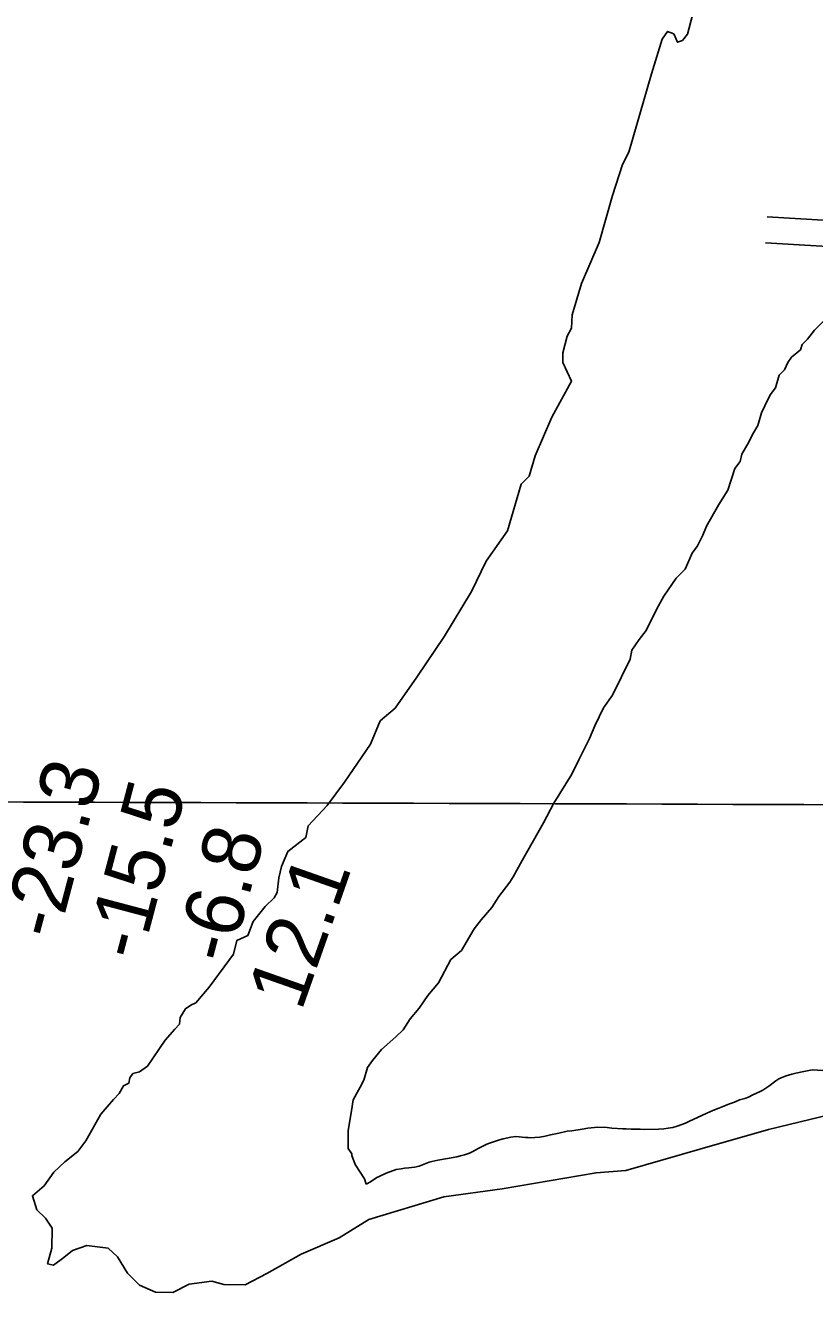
# Model space of a CAD drawing. Extents: x 3148686 to 3186545, y 916144 to 941516.
# Drawn here: x 3162509 to 3163416, y 933083 to 934539 of the extents above; entities that cross this region are included whole.
import ezdxf

# ---------------------------------------------------------------- set-up
doc = ezdxf.new("R2010")
doc.units = 0
for name, color, linetype in [('V-GRID-MAJR', 7, 'Continuous'), ('V-RIVR-EDGE', 7, 'Continuous'), ('V-RIVR-RANG', 7, 'Continuous'), ('V-ROAD-CNTR', 7, 'Continuous'), ('V-SITE-VEGE', 7, 'Continuous')]:
    doc.layers.add(name, color=color, linetype=linetype)

msp = doc.modelspace()

# ---------------------------------------------------------------- linework, layer by layer
at = {"layer": 'V-GRID-MAJR'}
msp.add_spline([(3152965.6, 933679.7), (3155575.1, 933670.5), (3160794.2, 933652.6), (3166013.2, 933635.6), (3171232.3, 933619.2), (3176451.4, 933603.7), (3181670.5, 933588.9), (3184280, 933581.8)], degree=3, dxfattribs=at)
at = {"layer": 'V-RIVR-EDGE'}
for points in [[(3162610.2, 933305.3), (3162616.9, 933312), (3162621.6, 933320.8), (3162627.9, 933323.9), (3162628.9, 933330.2), (3162632.6, 933334.8), (3162640.3, 933336.9), (3162649.2, 933343.6), (3162669.5, 933373.1), (3162680.9, 933386), (3162686.1, 933391.7), (3162686.7, 933399.5), (3162692.9, 933409.3), (3162699.1, 933413.5), (3162704.8, 933416.1), (3162720.4, 933434.2), (3162748, 933472), (3162752.2, 933488), (3162764.7, 933493.7), (3162770.9, 933509.8), (3162784.5, 933526.9), (3162794.9, 933536.7), (3162798.5, 933542.9), (3162800.1, 933560), (3162803.3, 933573), (3162810.6, 933590.1), (3162831.3, 933606.1), (3162834, 933619.6), (3162855.8, 933642.8), (3162875.6, 933669.8), (3162905.8, 933713.3), (3162916.7, 933740.2), (3162933.9, 933754.7), (3162958.9, 933790.4), (3162990.6, 933837.5), (3163021.9, 933888.8), (3163038.5, 933923.5), (3163063, 933958.7), (3163078.7, 934012.1), (3163088, 934021.4), (3163094.8, 934044.7), (3163114.1, 934089.3), (3163136.6, 934130.7), (3163126.7, 934152), (3163126.8, 934162.9), (3163131.5, 934182.1), (3163136.7, 934191.4), (3163137.3, 934206.9), (3163148.2, 934242.7), (3163168.6, 934289.8), (3163183.8, 934343.7), (3163195.3, 934379.5), (3163202.5, 934393.5), (3163228.7, 934483.6), (3163240.7, 934523.6), (3163247, 934532.4), (3163254.2, 934529.7), (3163258.4, 934519.9), (3163264.1, 934521.9), (3163269.8, 934529.2), (3163280.3, 934569.1)], [(3163469, 933296.4), (3163363.1, 933270.8), (3163284.3, 933248.2), (3163199.1, 933223.5), (3163164.9, 933221), (3163057, 933202.6), (3162990.1, 933193.4), (3162903.9, 933167.1), (3162869.6, 933146), (3162826, 933127.4), (3162786.5, 933105.2), (3162761.6, 933092.3), (3162737.2, 933092.4), (3162723.2, 933096.5), (3162697.3, 933093), (3162678.6, 933083.2), (3162658.4, 933083.7), (3162640.3, 933091.6), (3162626.3, 933105.6), (3162614.9, 933124.3), (3162604.1, 933134.2), (3162579.7, 933137.4), (3162563.1, 933131.7), (3162553.2, 933123.4), (3162541.3, 933114.6), (3162534.5, 933116.2), (3162539.2, 933134.3), (3162539.8, 933157.2), (3162532.1, 933168.6), (3162522.2, 933178.5), (3162517.1, 933194.6), (3162530.6, 933205.9), (3162541.5, 933221.5), (3162554.5, 933233.4), (3162569.1, 933245.3), (3162578.4, 933257.7), (3162595.6, 933288.2), (3162610.2, 933305.3)]]:
    msp.add_lwpolyline(points, dxfattribs=at)
at = {"layer": 'V-ROAD-CNTR'}
for points in [[(3163359.7, 934289.3), (3163482.6, 934282.1), (3164073.4, 934278.5), (3164714, 934271.7), (3165132.2, 934269.7), (3165570.2, 934275.6), (3166245.6, 934279.1), (3166867.8, 934288.1), (3167164.8, 934288.7), (3167686.9, 934273), (3168000.9, 934271.8), (3168168.6, 934286.1), (3168244.2, 934321), (3168298.4, 934368), (3168350.1, 934433.6), (3168384.1, 934490.5), (3168443.5, 934622.3), (3168480, 934725.3), (3168496.7, 934826), (3168498.8, 934894.8), (3168492.4, 935008.7), (3168468.4, 935145), (3168439.1, 935248.4)], [(3163361.5, 934319.2), (3163483.6, 934312.1), (3164073.6, 934308.5), (3164714.2, 934301.7), (3165132.1, 934299.7), (3165235.8, 934301.1)]]:
    msp.add_lwpolyline(points, dxfattribs=at)
at = {"layer": 'V-SITE-VEGE'}
for p, q in [((3163428.4, 934201.6), (3163416.1, 934189.2)), ((3163416.1, 934189.2), (3163407.9, 934178.8)), ((3163399.8, 934166.4), (3163389.5, 934158.1)), ((3163401.8, 934172.6), (3163399.8, 934166.4)), ((3163407.9, 934178.8), (3163401.8, 934172.6)), ((3163385.4, 934151.9), (3163381.4, 934143.7)), ((3163389.5, 934158.1), (3163385.4, 934151.9)), ((3163375.2, 934137.4), (3163371.2, 934123)), ((3163381.4, 934143.7), (3163375.2, 934137.4)), ((3163371.2, 934123), (3163365.1, 934114.7)), ((3163365.1, 934114.7), (3163359, 934102.3)), ((3163354.9, 934094.1), (3163350.9, 934079.6)), ((3163359, 934102.3), (3163354.9, 934094.1)), ((3163350.9, 934079.6), (3163344.7, 934069.3)), ((3163344.7, 934069.3), (3163340.7, 934061)), ((3163340.7, 934061), (3163332.5, 934046.6)), ((3163330.5, 934038.3), (3163324.4, 934030)), ((3163332.5, 934046.6), (3163330.5, 934038.3)), ((3163324.4, 934030), (3163316.3, 934005.3)), ((3163316.3, 934005.3), (3163306.1, 933988.7)), ((3163306.1, 933988.7), (3163291.8, 933964)), ((3163291.8, 933964), (3163287.7, 933953.6)), ((3163287.7, 933953.6), (3163281.6, 933941.2)), ((3163275.5, 933933), (3163267.4, 933914.4)), ((3163281.6, 933941.2), (3163275.5, 933933)), ((3163257.1, 933904), (3163242.8, 933883.3)), ((3163267.4, 933914.4), (3163257.1, 933904)), ((3163242.8, 933883.3), (3163234.7, 933868.9)), ((3163234.7, 933868.9), (3163222.5, 933844.1)), ((3163214.3, 933833.8), (3163206.1, 933821.3)), ((3163222.5, 933844.1), (3163214.3, 933833.8)), ((3163206.1, 933821.3), (3163204.1, 933811)), ((3163204.1, 933811), (3163183.8, 933769.7)), ((3163183.8, 933769.7), (3163173.5, 933755.3)), ((3163173.5, 933755.3), (3163163.4, 933734.6)), ((3163163.4, 933734.6), (3163157.3, 933720.1)), ((3163157.3, 933720.1), (3163145.1, 933695.4)), ((3163145.1, 933695.4), (3163136.9, 933678.8)), ((3163136.9, 933678.8), (3163116.5, 933645.8)), ((3163116.5, 933645.8), (3163104.3, 933623)), ((3163104.3, 933623), (3163079.8, 933579.6)), ((3163079.8, 933579.6), (3163069.6, 933561)), ((3163065.6, 933554.8), (3163053.3, 933538.3)), ((3163069.6, 933561), (3163065.6, 933554.8)), ((3163045.1, 933525.9), (3163032.8, 933511.4)), ((3163053.3, 933538.3), (3163045.1, 933525.9)), ((3163032.8, 933511.4), (3163024.7, 933501.1)), ((3163024.7, 933501.1), (3163010.4, 933476.3)), ((3163010.4, 933476.3), (3162998.1, 933465.9)), ((3162998.1, 933465.9), (3162983.8, 933439)), ((3162983.8, 933439), (3162971.6, 933424.5)), ((3162971.6, 933424.5), (3162961.4, 933410.1)), ((3162961.4, 933410.1), (3162951.1, 933397.7)), ((3162951.1, 933397.7), (3162943, 933385.2)), ((3162943, 933385.2), (3162934.8, 933377)), ((3162934.8, 933377), (3162918.4, 933362.4)), ((3162908.1, 933350), (3162902, 933341.8)), ((3162918.4, 933362.4), (3162908.1, 933350)), ((3162902, 933341.8), (3162898, 933327.3)), ((3163389.7, 933334.3), (3163394.4, 933335.5)), ((3163394.4, 933335.5), (3163403.5, 933337.4)), ((3163403.5, 933337.4), (3163413.3, 933339.1)), ((3163413.3, 933339.1), (3163425.7, 933338.6)), ((3162898, 933327.3), (3162893.9, 933319.1)), ((3163363.5, 933320.6), (3163371.6, 933326.6)), ((3163371.6, 933326.6), (3163374.9, 933328.8)), ((3163374.9, 933328.8), (3163377.7, 933330.1)), ((3163377.7, 933330.1), (3163383.4, 933332.4)), ((3163383.4, 933332.4), (3163389.7, 933334.3)), ((3162893.9, 933319.1), (3162885.8, 933304.6)), ((3163335.7, 933306.1), (3163340, 933307.8)), ((3163340, 933307.8), (3163345.1, 933310.3)), ((3163345.1, 933310.3), (3163353.6, 933314.2)), ((3163353.6, 933314.2), (3163356.4, 933315.7)), ((3163356.4, 933315.7), (3163363.5, 933320.6)), ((3162883.8, 933292.2), (3162879.8, 933269.5)), ((3162885.8, 933304.6), (3162883.8, 933292.2)), ((3163292.1, 933289.5), (3163299.2, 933292.4)), ((3163299.2, 933292.4), (3163305.9, 933295.3)), ((3163305.9, 933295.3), (3163311.6, 933297.4)), ((3163311.6, 933297.4), (3163316.5, 933299.5)), ((3163316.5, 933299.5), (3163319.5, 933300.7)), ((3163319.5, 933300.7), (3163324, 933302.2)), ((3163324, 933302.2), (3163329.6, 933304.6)), ((3163329.6, 933304.6), (3163335.7, 933306.1)), ((3163258.2, 933274.5), (3163267.5, 933277.9)), ((3163267.5, 933277.9), (3163271.4, 933279.9)), ((3163271.4, 933279.9), (3163292.1, 933289.5)), ((3162879.8, 933269.5), (3162879.9, 933249)), ((3163100.4, 933261.7), (3163106.5, 933262.9)), ((3163106.5, 933262.9), (3163112.6, 933264.6)), ((3163112.6, 933264.6), (3163122, 933266.3)), ((3163122, 933266.3), (3163131.6, 933268.6)), ((3163131.6, 933268.6), (3163137, 933269.3)), ((3163137, 933269.3), (3163148.8, 933271.2)), ((3163148.8, 933271.2), (3163155.4, 933272.1)), ((3163155.4, 933272.1), (3163166.8, 933273.2)), ((3163166.8, 933273.2), (3163177.5, 933273.1)), ((3163177.5, 933273.1), (3163183.1, 933272.3)), ((3163183.1, 933272.3), (3163195.5, 933271.4)), ((3163195.5, 933271.4), (3163199.4, 933271.4)), ((3163199.4, 933271.4), (3163205.1, 933270.9)), ((3163205.1, 933270.9), (3163215.7, 933270.9)), ((3163215.7, 933270.9), (3163220.1, 933270.6)), ((3163220.1, 933270.6), (3163236.6, 933270.9)), ((3163236.6, 933270.9), (3163242.9, 933271.6)), ((3163242.9, 933271.6), (3163247.6, 933272)), ((3163247.6, 933272), (3163253.1, 933272.9)), ((3163253.1, 933272.9), (3163258.2, 933274.5)), ((3162879.9, 933249), (3162884.1, 933242.8)), ((3163024.2, 933245.8), (3163029.5, 933248.7)), ((3163029.5, 933248.7), (3163039.4, 933253.8)), ((3163039.4, 933253.8), (3163042.4, 933255.1)), ((3163042.4, 933255.1), (3163048.1, 933257)), ((3163048.1, 933257), (3163053.8, 933258.8)), ((3163053.8, 933258.8), (3163058.1, 933259.9)), ((3163058.1, 933259.9), (3163067, 933262)), ((3163067, 933262), (3163072.7, 933262.5)), ((3163072.7, 933262.5), (3163083.7, 933261.5)), ((3163083.7, 933261.5), (3163087, 933261.4)), ((3163087, 933261.4), (3163090.1, 933261.2)), ((3163090.1, 933261.2), (3163094.7, 933261.4)), ((3163094.7, 933261.4), (3163100.4, 933261.7)), ((3162884.1, 933242.8), (3162884.1, 933240.7)), ((3162884.1, 933240.7), (3162888.2, 933230.5)), ((3162973, 933233.1), (3162976.2, 933234)), ((3162976.2, 933234), (3162982.9, 933235.5)), ((3162982.9, 933235.5), (3162994.1, 933237.2)), ((3162994.1, 933237.2), (3163004.7, 933239.3)), ((3163004.7, 933239.3), (3163009, 933240.2)), ((3163009, 933240.2), (3163013.8, 933241.6)), ((3163013.8, 933241.6), (3163019.3, 933243.5)), ((3163019.3, 933243.5), (3163024.2, 933245.8)), ((3162888.2, 933230.5), (3162898.6, 933214)), ((3162915.5, 933216.8), (3162923.6, 933220.3)), ((3162923.6, 933220.3), (3162935, 933224.5)), ((3162935, 933224.5), (3162940.8, 933225.6)), ((3162940.8, 933225.6), (3162944.7, 933226.2)), ((3162944.7, 933226.2), (3162949.6, 933226.6)), ((3162949.6, 933226.6), (3162956.3, 933227.3)), ((3162956.3, 933227.3), (3162961.6, 933228.6)), ((3162961.6, 933228.6), (3162973, 933233.1)), ((3162898.6, 933214), (3162900.7, 933207.9)), ((3162900.7, 933207.9), (3162905.5, 933210.6)), ((3162905.5, 933210.6), (3162912.8, 933215.3)), ((3162912.8, 933215.3), (3162915.5, 933216.8))]:
    msp.add_line(p, q, dxfattribs=at)

# ---------------------------------------------------------------- texts
at = {"layer": 'V-RIVR-RANG'}
for s, rotation, p in [('-23.3', 75.1814, (3162546, 933486.7)), ('-15.5', 75.1814, (3162641.8, 933462.5)), ('-6.8', 75.1814, (3162745.1, 933458.8)), ('12.1', 70.6283, (3162826.1, 933405.4))]:
    msp.add_text(s, height=67, rotation=rotation, dxfattribs=at).set_placement(p)

doc.saveas('drawing.dxf')
